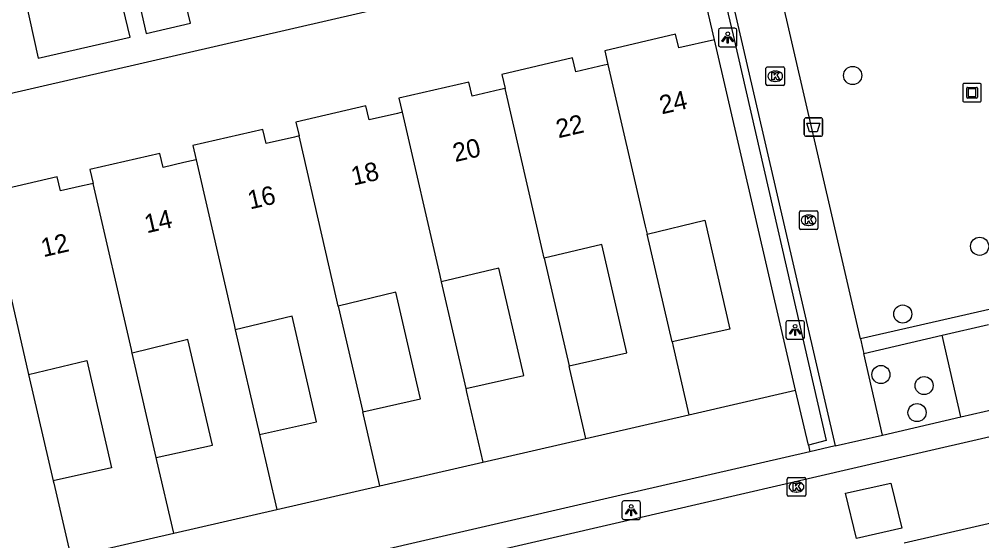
# Model space of a CAD drawing. Extents: x 156414 to 157775, y 382335 to 383765.
# Drawn here: x 156758.1 to 156810, y 382711.6 to 382739.7 of the extents above; entities that cross this region are included whole.
import ezdxf

# ---------------------------------------------------------------- set-up
doc = ezdxf.new("R2010")
doc.units = 0
for name, color, linetype in [('IMGEO_Afvalbak', 7, 'Continuous'), ('IMGEO_Boom', 7, 'Continuous'), ('IMGEO_Groenvoorziening', 7, 'Continuous'), ('IMGEO_Haag', 7, 'Continuous'), ('IMGEO_Kolk', 7, 'Continuous'), ('IMGEO_Kunstobject', 7, 'Continuous'), ('IMGEO_Lichtpunt', 7, 'Continuous'), ('IMGEO_Muur', 7, 'Continuous'), ('IMGEO_Pand', 7, 'Continuous'), ('IMGEO_Pand_nummerreeks', 7, 'Continuous'), ('IMGEO_Parkeervlak_open', 7, 'Continuous'), ('IMGEO_Rijbaan_lokaal_open', 7, 'Continuous'), ('IMGEO_Voetpad_open', 7, 'Continuous')]:
    doc.layers.add(name, color=color, linetype=linetype)

msp = doc.modelspace()

# ---------------------------------------------------------------- linework, layer by layer
at = {"layer": 'IMGEO_Afvalbak'}
for p, q in [((156800.462, 382733.511), (156800.462, 382734.311)), ((156800.462, 382734.311), (156800.462, 382733.511)), ((156800.562, 382734.411), (156801.352, 382734.411)), ((156801.352, 382734.411), (156800.562, 382734.411)), ((156801.452, 382734.311), (156801.452, 382733.511)), ((156801.452, 382733.511), (156801.452, 382734.311)), ((156801.352, 382733.411), (156800.562, 382733.411)), ((156800.562, 382733.411), (156801.352, 382733.411))]:
    msp.add_line(p, q, dxfattribs=at)
msp.add_lwpolyline([(156800.605, 382734.125), (156801.309, 382734.125), (156801.16, 382733.655), (156800.754, 382733.655), (156800.605, 382734.125)], dxfattribs=at)
for centre, start, end in [((156800.562, 382734.311), 90, 180), ((156800.562, 382734.311), 90, 180), ((156801.352, 382734.311), 0, 90), ((156801.352, 382734.311), 360, 90), ((156800.562, 382733.511), 180, 270), ((156800.562, 382733.511), 180, 270), ((156801.352, 382733.511), 270, 0), ((156801.352, 382733.511), 270, 0)]:
    msp.add_arc(centre, 0.1, start, end, dxfattribs=at)
at = {"layer": 'IMGEO_Boom'}
for centre in [(156803.074, 382736.692), (156809.918, 382727.482), (156805.775, 382723.827), (156804.597, 382720.564), (156806.924, 382719.969), (156806.543, 382718.514)]:
    msp.add_circle(centre, 0.489, dxfattribs=at)
at = {"layer": 'IMGEO_Groenvoorziening'}
for points in [[(156795.633, 382738.617), (156794.426, 382743.797)], [(156800.687, 382716.754), (156799.998, 382719.724)]]:
    msp.add_lwpolyline(points, dxfattribs=at)
at = {"layer": 'IMGEO_Haag'}
msp.add_lwpolyline([(156834.402, 382729.53), (156803.492, 382722.496)], dxfattribs=at)
at = {"layer": 'IMGEO_Kolk'}
for p, q in [((156798.472, 382737.153), (156799.324, 382737.153)), ((156798.397, 382736.227), (156798.397, 382737.079)), ((156798.885, 382736.933), (156798.91, 382736.933)), ((156799.398, 382737.079), (156799.398, 382736.227)), ((156799.324, 382736.153), (156798.472, 382736.153)), ((156798.908, 382736.373), (156798.883, 382736.373)), ((156800.277, 382729.388), (156801.129, 382729.388)), ((156800.202, 382728.462), (156800.202, 382729.314)), ((156800.69, 382729.168), (156800.715, 382729.168)), ((156801.203, 382729.314), (156801.203, 382728.462)), ((156801.129, 382728.388), (156800.277, 382728.388)), ((156800.713, 382728.608), (156800.688, 382728.608)), ((156799.545, 382714.077), (156799.545, 382714.929)), ((156799.62, 382715.003), (156800.472, 382715.003)), ((156800.546, 382714.929), (156800.546, 382714.077)), ((156800.033, 382714.783), (156800.058, 382714.783)), ((156800.472, 382714.003), (156799.62, 382714.003)), ((156800.056, 382714.223), (156800.031, 382714.223))]:
    msp.add_line(p, q, dxfattribs=at)
for points in [[(156798.472, 382737.153), (156799.324, 382737.153)], [(156798.397, 382736.227), (156798.397, 382737.079)], [(156798.718, 382736.853), (156798.841, 382736.853), (156798.841, 382736.702), (156798.971, 382736.853), (156799.135, 382736.853), (156798.989, 382736.702), (156799.142, 382736.453), (156798.99, 382736.453), (156798.905, 382736.617), (156798.841, 382736.55), (156798.841, 382736.453), (156798.718, 382736.453), (156798.718, 382736.853)], [(156799.398, 382737.079), (156799.398, 382736.227)], [(156799.324, 382736.153), (156798.472, 382736.153)], [(156800.277, 382729.388), (156801.129, 382729.388)], [(156800.202, 382728.462), (156800.202, 382729.314)], [(156800.523, 382729.088), (156800.646, 382729.088), (156800.646, 382728.937), (156800.776, 382729.088), (156800.94, 382729.088), (156800.794, 382728.937), (156800.947, 382728.688), (156800.795, 382728.688), (156800.71, 382728.852), (156800.646, 382728.785), (156800.646, 382728.688), (156800.523, 382728.688), (156800.523, 382729.088)], [(156801.203, 382729.314), (156801.203, 382728.462)], [(156801.129, 382728.388), (156800.277, 382728.388)], [(156799.545, 382714.077), (156799.545, 382714.929)], [(156799.62, 382715.003), (156800.472, 382715.003)], [(156800.546, 382714.929), (156800.546, 382714.077)], [(156799.866, 382714.703), (156799.989, 382714.703), (156799.989, 382714.552), (156800.119, 382714.703), (156800.283, 382714.703), (156800.137, 382714.552), (156800.29, 382714.303), (156800.138, 382714.303), (156800.053, 382714.467), (156799.989, 382714.4), (156799.989, 382714.303), (156799.866, 382714.303), (156799.866, 382714.703)], [(156800.472, 382714.003), (156799.62, 382714.003)]]:
    msp.add_lwpolyline(points, dxfattribs=at)
for centre, start, end in [((156798.474, 382737.077), 91.552, 178.448), ((156798.474, 382737.077), 91.552, 178.448), ((156799.322, 382737.077), 1.552, 88.448), ((156799.322, 382737.077), 1.552, 88.448), ((156798.474, 382736.229), 181.552, 268.448), ((156798.474, 382736.229), 181.552, 268.448), ((156799.322, 382736.229), 271.552, 358.448), ((156799.322, 382736.229), 271.552, 358.448), ((156800.279, 382729.312), 91.552, 178.448), ((156800.279, 382729.312), 91.552, 178.448), ((156801.127, 382729.312), 1.552, 88.448), ((156801.127, 382729.312), 1.552, 88.448), ((156800.279, 382728.464), 181.552, 268.448), ((156800.279, 382728.464), 181.552, 268.448), ((156801.127, 382728.464), 271.552, 358.448), ((156801.127, 382728.464), 271.552, 358.448), ((156799.622, 382714.927), 91.552, 178.448), ((156799.622, 382714.927), 91.552, 178.448), ((156800.47, 382714.927), 1.552, 88.448), ((156800.47, 382714.927), 1.552, 88.448), ((156799.622, 382714.079), 181.552, 268.448), ((156799.622, 382714.079), 181.552, 268.448), ((156800.47, 382714.079), 271.552, 358.448), ((156800.47, 382714.079), 271.552, 358.448)]:
    msp.add_arc(centre, 0.0765, start, end, dxfattribs=at)
for centre, major_axis, ratio, start_param, end_param in [((156798.884, 382736.653), (-0.387, 0.002), 0.722429, 4.712389, 7.853982), ((156798.909, 382736.653), (-0.39, 0.002), 0.717154, 1.570796, 4.712389), ((156800.689, 382728.888), (-0.387, 0.002), 0.722429, 4.712389, 7.853982), ((156800.714, 382728.888), (-0.39, 0.002), 0.717154, 1.570796, 4.712389), ((156800.032, 382714.503), (-0.387, 0.002), 0.722429, 4.712389, 7.853982), ((156800.057, 382714.503), (-0.39, 0.002), 0.717154, 1.570796, 4.712389)]:
    msp.add_ellipse(centre, major_axis=major_axis, ratio=ratio, start_param=start_param, end_param=end_param, dxfattribs=at)
at = {"layer": 'IMGEO_Kunstobject'}
for p, q in [((156809.007, 382736.18), (156809.007, 382735.339)), ((156809.007, 382736.18), (156809.007, 382735.339)), ((156809.923, 382736.264), (156809.082, 382736.264)), ((156809.923, 382736.264), (156809.082, 382736.264)), ((156810.007, 382735.348), (156810.007, 382736.189)), ((156810.007, 382735.348), (156810.007, 382736.189)), ((156809.221, 382735.528), (156809.221, 382736.002)), ((156809.271, 382736.052), (156809.745, 382736.052)), ((156809.301, 382735.952), (156809.301, 382735.578)), ((156809.695, 382735.972), (156809.321, 382735.972)), ((156809.321, 382735.558), (156809.695, 382735.558)), ((156809.715, 382735.578), (156809.715, 382735.952)), ((156809.795, 382736.002), (156809.795, 382735.528)), ((156809.091, 382735.264), (156809.932, 382735.264)), ((156809.091, 382735.264), (156809.932, 382735.264)), ((156809.745, 382735.478), (156809.271, 382735.478))]:
    msp.add_line(p, q, dxfattribs=at)
for centre, radius, start, end in [((156809.085, 382736.186), 0.0779, 92.4484, 184.2845), ((156809.085, 382736.186), 0.0779, 92.4484, 184.2845), ((156809.929, 382736.186), 0.0779, 2.4484, 94.2845), ((156809.929, 382736.186), 0.0779, 2.4484, 94.2845), ((156809.271, 382736.002), 0.05, 90, 180), ((156809.321, 382735.952), 0.02, 90, 180), ((156809.321, 382735.578), 0.02, 180, 270), ((156809.695, 382735.952), 0.02, 360, 90), ((156809.695, 382735.578), 0.02, 270, 0), ((156809.745, 382736.002), 0.05, 360, 90), ((156809.085, 382735.342), 0.0779, 182.4484, 274.2845), ((156809.085, 382735.342), 0.0779, 182.4484, 274.2845), ((156809.271, 382735.528), 0.05, 180, 270), ((156809.745, 382735.528), 0.05, 270, 0), ((156809.929, 382735.342), 0.0779, 272.4484, 4.2845), ((156809.929, 382735.342), 0.0779, 272.4484, 4.2845)]:
    msp.add_arc(centre, radius, start, end, dxfattribs=at)
at = {"layer": 'IMGEO_Lichtpunt'}
for p, q in [((156796.74, 382739.236), (156795.932, 382739.236)), ((156796.74, 382739.236), (156795.932, 382739.236)), ((156795.838, 382739.141), (156795.838, 382738.334)), ((156795.838, 382739.141), (156795.838, 382738.334)), ((156796.834, 382738.334), (156796.834, 382739.141)), ((156796.834, 382738.334), (156796.834, 382739.141)), ((156795.932, 382738.24), (156796.74, 382738.24)), ((156795.932, 382738.24), (156796.74, 382738.24)), ((156799.473, 382723.374), (156799.473, 382722.567)), ((156799.473, 382723.374), (156799.473, 382722.567)), ((156800.375, 382723.469), (156799.567, 382723.469)), ((156800.375, 382723.469), (156799.567, 382723.469)), ((156800.469, 382722.567), (156800.469, 382723.374)), ((156800.469, 382722.567), (156800.469, 382723.374)), ((156799.567, 382722.473), (156800.375, 382722.473)), ((156799.567, 382722.473), (156800.375, 382722.473)), ((156790.636, 382713.652), (156790.636, 382712.845)), ((156790.636, 382713.652), (156790.636, 382712.845)), ((156791.538, 382713.747), (156790.73, 382713.747)), ((156791.538, 382713.747), (156790.73, 382713.747)), ((156791.632, 382712.845), (156791.632, 382713.652)), ((156791.632, 382712.845), (156791.632, 382713.652)), ((156790.73, 382712.751), (156791.538, 382712.751)), ((156790.73, 382712.751), (156791.538, 382712.751))]:
    msp.add_line(p, q, dxfattribs=at)
for points in [[(156796.212, 382738.805), (156796.251, 382738.777), (156796.063, 382738.515), (156796.025, 382738.542), (156796.212, 382738.805)], [(156796.314, 382738.757), (156796.361, 382738.757), (156796.361, 382738.435), (156796.314, 382738.435), (156796.314, 382738.757)], [(156796.424, 382738.777), (156796.462, 382738.804), (156796.649, 382738.542), (156796.61, 382738.514), (156796.424, 382738.777)], [(156799.847, 382723.038), (156799.886, 382723.01), (156799.698, 382722.748), (156799.66, 382722.775), (156799.847, 382723.038)], [(156799.949, 382722.99), (156799.996, 382722.99), (156799.996, 382722.668), (156799.949, 382722.668), (156799.949, 382722.99)], [(156800.059, 382723.01), (156800.097, 382723.037), (156800.284, 382722.775), (156800.245, 382722.747), (156800.059, 382723.01)], [(156791.01, 382713.316), (156791.049, 382713.288), (156790.861, 382713.026), (156790.823, 382713.053), (156791.01, 382713.316)], [(156791.112, 382713.268), (156791.159, 382713.268), (156791.159, 382712.946), (156791.112, 382712.946), (156791.112, 382713.268)], [(156791.222, 382713.288), (156791.26, 382713.315), (156791.447, 382713.053), (156791.408, 382713.025), (156791.222, 382713.288)]]:
    msp.add_lwpolyline(points, dxfattribs=at)
for centre in [(156796.337, 382738.939), (156799.972, 382723.172), (156791.135, 382713.45)]:
    msp.add_circle(centre, 0.0994, dxfattribs=at)
for centre, start, end in [((156795.932, 382739.141), 90, 180), ((156795.932, 382739.141), 90, 180), ((156796.74, 382739.141), 0, 90), ((156796.74, 382739.141), 0, 90), ((156795.932, 382738.334), 180, 270), ((156795.932, 382738.334), 180, 270), ((156796.74, 382738.334), 270, 0), ((156796.74, 382738.334), 270, 360), ((156799.567, 382723.374), 90, 180), ((156799.567, 382723.374), 90, 180), ((156800.375, 382723.374), 0, 90), ((156800.375, 382723.374), 0, 90), ((156799.567, 382722.567), 180, 270), ((156799.567, 382722.567), 180, 270), ((156800.375, 382722.567), 270, 0), ((156800.375, 382722.567), 270, 360), ((156790.73, 382713.652), 90, 180), ((156790.73, 382713.652), 90, 180), ((156791.538, 382713.652), 0, 90), ((156791.538, 382713.652), 0, 90), ((156790.73, 382712.845), 180, 270), ((156790.73, 382712.845), 180, 270), ((156791.538, 382712.845), 270, 0), ((156791.538, 382712.845), 270, 360)]:
    msp.add_arc(centre, 0.0946, start, end, dxfattribs=at)
at = {"layer": 'IMGEO_Muur'}
for points in [[(156795.712, 382744.485), (156802.123, 382716.713)], [(156794.426, 382743.797), (156795.403, 382744.032), (156796.63, 382738.862), (156801.644, 382717.012), (156800.687, 382716.754)], [(156800.687, 382716.754), (156800.769, 382716.402)], [(156802.123, 382716.713), (156800.769, 382716.402)]]:
    msp.add_lwpolyline(points, dxfattribs=at)
at = {"layer": 'IMGEO_Pand'}
for points in [[(156795.633, 382738.617), (156793.695, 382738.186), (156793.515, 382738.921), (156789.714, 382738.026), (156789.883, 382737.292)], [(156799.998, 382719.724), (156795.633, 382738.617)], [(156789.883, 382737.292), (156789.675, 382737.244), (156788.148, 382736.89), (156787.973, 382737.649), (156784.162, 382736.744), (156784.335, 382735.993)], [(156789.883, 382737.292), (156791.894, 382728.574), (156791.995, 382728.14)], [(156784.335, 382735.993), (156784.085, 382735.935), (156782.558, 382735.581), (156782.383, 382736.34), (156778.609, 382735.464), (156778.783, 382734.708)], [(156786.447, 382726.837), (156786.354, 382727.241), (156784.335, 382735.993)], [(156778.783, 382734.708), (156778.533, 382734.65), (156777.006, 382734.296), (156776.831, 382735.055), (156773.056, 382734.182), (156773.229, 382733.431)], [(156778.783, 382734.708), (156780.812, 382725.907), (156780.893, 382725.557)], [(156773.229, 382733.431), (156772.986, 382733.375), (156771.459, 382733.021), (156771.284, 382733.78), (156767.5, 382732.913), (156767.677, 382732.144)], [(156775.346, 382724.25), (156775.272, 382724.574), (156773.229, 382733.431)], [(156767.677, 382732.144), (156767.434, 382732.088), (156767.021, 382731.992), (156765.907, 382731.734), (156765.732, 382732.493), (156761.951, 382731.616), (156762.123, 382730.869)], [(156767.677, 382732.144), (156769.73, 382723.24), (156769.791, 382722.977)], [(156762.123, 382730.869), (156761.898, 382730.817), (156761.558, 382730.738), (156760.371, 382730.463), (156760.196, 382731.222), (156756.396, 382730.342), (156756.57, 382729.588)], [(156764.232, 382721.721), (156764.19, 382721.906), (156762.123, 382730.869)], [(156756.57, 382729.588), (156758.648, 382720.573)], [(156791.995, 382728.14), (156795.105, 382728.888), (156796.459, 382723.019), (156793.335, 382722.33)], [(156793.335, 382722.33), (156791.995, 382728.14)], [(156787.784, 382721.041), (156790.901, 382721.73), (156789.551, 382727.585), (156786.447, 382726.837)], [(156786.447, 382726.837), (156787.784, 382721.041)], [(156782.217, 382719.815), (156785.342, 382720.506), (156784.005, 382726.306), (156780.893, 382725.557)], [(156780.893, 382725.557), (156782.217, 382719.815)], [(156776.66, 382718.554), (156779.777, 382719.26), (156779.584, 382720.099), (156778.454, 382724.998), (156775.346, 382724.25)], [(156775.346, 382724.25), (156776.66, 382718.554)], [(156771.093, 382717.325), (156774.178, 382718.006), (156772.862, 382723.716), (156769.791, 382722.977)], [(156769.791, 382722.977), (156771.093, 382717.325)], [(156765.53, 382716.091), (156768.554, 382716.758), (156767.242, 382722.445), (156764.232, 382721.721)], [(156793.335, 382722.33), (156793.394, 382722.076), (156794.242, 382718.399)], [(156765.53, 382716.091), (156764.232, 382721.721)], [(156758.648, 382720.573), (156761.782, 382721.327), (156763.119, 382715.525), (156759.971, 382714.83)], [(156788.688, 382717.12), (156787.828, 382720.847), (156787.784, 382721.041)], [(156758.648, 382720.573), (156759.971, 382714.83)], [(156782.217, 382719.815), (156782.262, 382719.618), (156783.133, 382715.842)], [(156794.242, 382718.399), (156799.998, 382719.724)], [(156777.58, 382714.563), (156776.698, 382718.39), (156776.66, 382718.554)], [(156788.688, 382717.12), (156794.242, 382718.399)], [(156771.093, 382717.325), (156771.131, 382717.161), (156772.025, 382713.284)], [(156783.133, 382715.842), (156788.688, 382717.12)], [(156766.472, 382712.006), (156765.567, 382715.932), (156765.53, 382716.091)], [(156777.58, 382714.563), (156783.133, 382715.842)], [(156759.971, 382714.83), (156760.001, 382714.703), (156760.917, 382710.727)], [(156772.025, 382713.284), (156777.58, 382714.563)], [(156766.472, 382712.006), (156772.025, 382713.284)], [(156760.917, 382710.727), (156766.472, 382712.006)]]:
    msp.add_lwpolyline(points, dxfattribs=at)
at = {"layer": 'IMGEO_Parkeervlak_open'}
msp.add_lwpolyline([(156807.895, 382722.68), (156810.39, 382723.256)], dxfattribs=at)
at = {"layer": 'IMGEO_Rijbaan_lokaal_open'}
for points in [[(156730.522, 382698.738), (156791.204, 382712.755), (156805.031, 382715.955), (156830.401, 382721.812), (156868.803, 382730.665), (156879.275, 382733.088), (156907.413, 382739.578), (156929.495, 382744.678), (156949.815, 382749.383)], [(156805.847, 382711.483), (156831.783, 382717.455), (156841.152, 382719.616), (156876.422, 382727.751)], [(156805.717, 382712.279), (156803.281, 382711.716), (156802.681, 382714.158), (156805.139, 382714.707), (156805.717, 382712.279)]]:
    msp.add_lwpolyline(points, dxfattribs=at)
at = {"layer": 'IMGEO_Voetpad_open'}
for points in [[(156803.492, 382722.496), (156798.417, 382744.512)], [(156794.348, 382744.171), (156723.806, 382727.923)], [(156764.008, 382743.229), (156764.993, 382738.959), (156767.373, 382739.508), (156766.346, 382743.769)], [(156758.224, 382741.895), (156759.172, 382737.618), (156764.127, 382738.76), (156763.1, 382743.02)], [(156803.674, 382721.707), (156807.895, 382722.68)], [(156808.902, 382718.276), (156807.895, 382722.68)], [(156803.492, 382722.496), (156803.627, 382721.911), (156803.674, 382721.707)], [(156804.689, 382717.303), (156803.674, 382721.707)], [(156808.902, 382718.276), (156811.426, 382718.859)], [(156804.689, 382717.303), (156808.902, 382718.276)], [(156802.123, 382716.713), (156804.689, 382717.303)], [(156800.769, 382716.402), (156790.128, 382713.958), (156730.2, 382700.114)]]:
    msp.add_lwpolyline(points, dxfattribs=at)

# ---------------------------------------------------------------- texts
at = {"layer": 'IMGEO_Pand_nummerreeks'}
for s, p in [('24', (156792.782, 382734.592)), ('22', (156787.208, 382733.304)), ('20', (156781.644, 382732.018)), ('18', (156776.163, 382730.752)), ('16', (156770.589, 382729.464)), ('14', (156765.019, 382728.177)), ('12', (156759.445, 382726.89))]:
    msp.add_text(s, height=1, rotation=13.0119, dxfattribs=at).set_placement(p)

doc.saveas('drawing.dxf')
